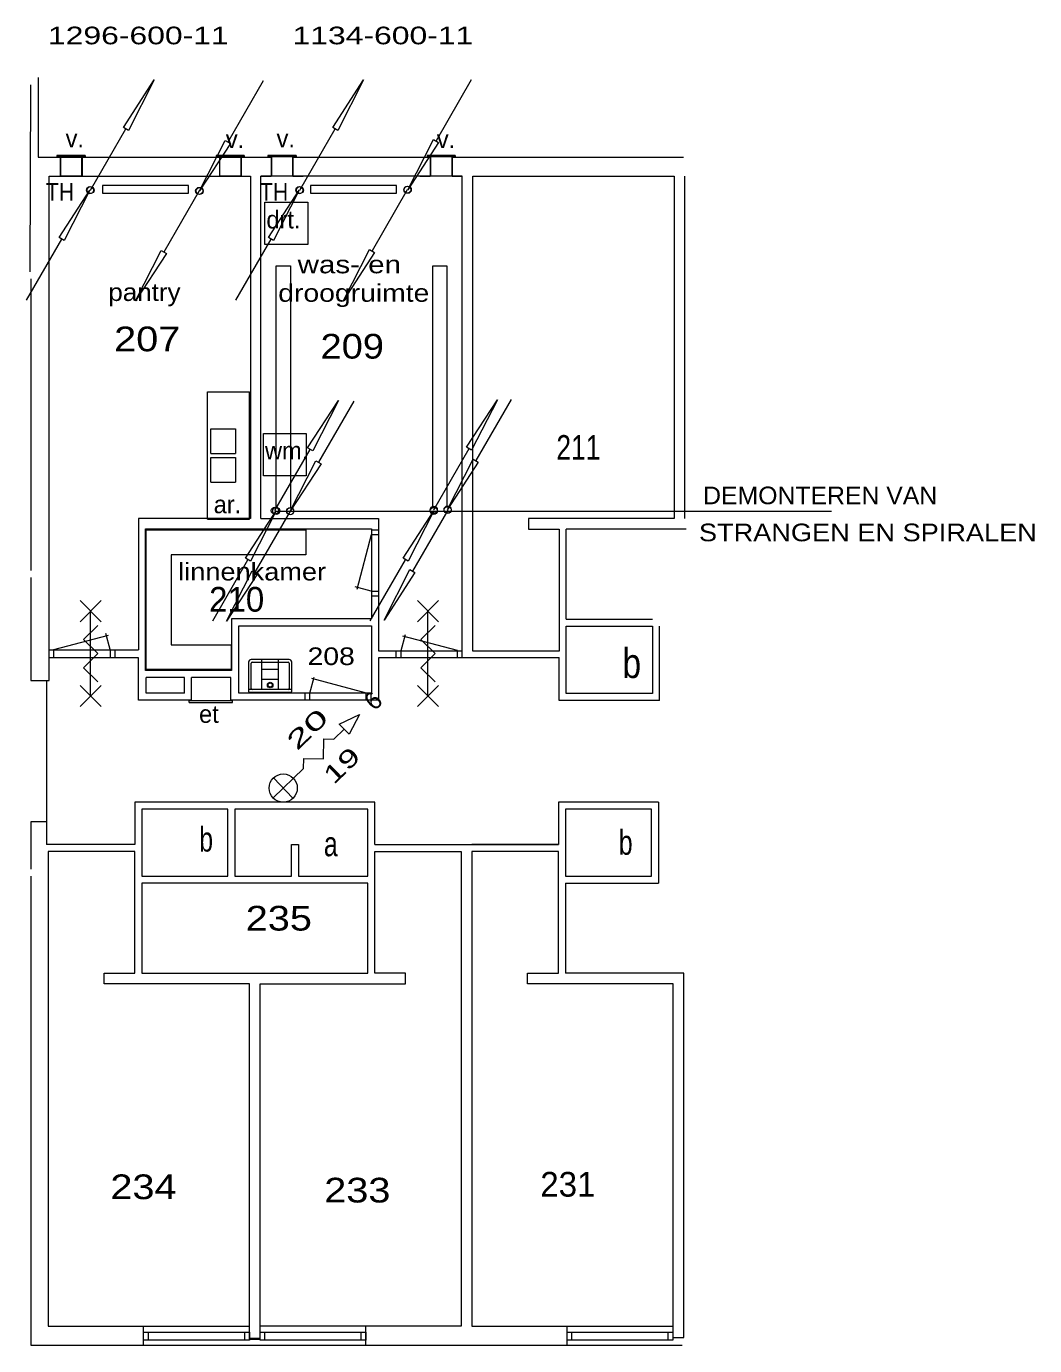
# Model space of a CAD drawing. Extents: x 295824 to 414724, y 24924 to 109024.
# Drawn here: x 361003 to 375282, y 62517 to 81204 of the extents above; entities that cross this region are included whole.
import ezdxf
from ezdxf.enums import TextEntityAlignment as Align

# ---------------------------------------------------------------- set-up
doc = ezdxf.new("R2010")
doc.units = 0
doc.header["$LTSCALE"] = 100
doc.layers.add('16', color=7, linetype='Continuous', lineweight=13)
doc.layers.add('61', color=7, linetype='Continuous', lineweight=13)

msp = doc.modelspace()

# ---------------------------------------------------------------- linework, layer by layer
at = {"layer": '16'}
for p, q in [((364356.3, 80430.9), (363856.3, 79564.9)), ((367304.4, 80447.6), (366804.4, 79581.6)), ((361912.5, 78885.4), (362412.5, 79751.4)), ((364877.3, 78885.4), (365377.3, 79751.4)), ((363450.2, 78872.9), (362950.2, 78006.9)), ((366398.3, 78889.6), (365898.3, 78023.6)), ((361003.2, 77324.8), (361503.2, 78190.8)), ((363968.1, 77324.8), (364468.1, 78190.8)), ((365640.7, 75894.7), (365140.7, 75028.7)), ((367867.8, 75918.5), (367367.8, 75052.5)), ((364522.2, 74344.5), (365022.2, 75210.5)), ((366773.1, 74356.4), (367273.1, 75222.4)), ((364738.5, 74336.4), (364238.5, 73470.4)), ((364519.8, 74337.8), (372403.9, 74337.8)), ((366970.5, 74353.1), (366470.5, 73487.1)), ((363641.4, 72782), (364141.4, 73648)), ((365873.4, 72782), (366373.4, 73648))]:
    msp.add_line(p, q, dxfattribs=at)
for points in [[(362812.5, 80444.4), (362448.5, 79730.4), (362376.5, 79772.4)], [(365777.3, 80444.4), (365413.3, 79730.4), (365341.3, 79772.4)], [(363456.3, 78871.9), (363820.3, 79585.9), (363892.3, 79543.9)], [(366404.4, 78888.6), (366768.4, 79602.6), (366840.4, 79560.6)], [(361903.2, 78883.8), (361539.2, 78169.8), (361467.2, 78211.8)], [(362080.8, 78843), (363297.5, 78843), (363297.5, 78950.2), (362080.8, 78950.2)], [(364868.1, 78883.8), (364504.1, 78169.8), (364432.1, 78211.8)], [(365026.2, 78843), (366242.9, 78843), (366242.9, 78950.2), (365026.2, 78950.2)], [(362550.2, 77313.9), (362914.2, 78027.9), (362986.2, 77985.9)], [(365498.3, 77330.6), (365862.3, 78044.6), (365934.3, 78002.6)], [(365422.2, 75903.5), (365058.2, 75189.5), (364986.2, 75231.5)], [(367673.1, 75915.4), (367309.1, 75201.4), (367237.1, 75243.4)], [(364740.7, 74335.7), (365104.7, 75049.7), (365176.7, 75007.7)], [(366967.8, 74359.5), (367331.8, 75073.5), (367403.8, 75031.5)], [(364541.4, 74341), (364177.4, 73627), (364105.4, 73669)], [(366773.4, 74341), (366409.4, 73627), (366337.4, 73669)], [(363838.5, 72777.4), (364202.5, 73491.4), (364274.5, 73449.4)], [(366070.5, 72794.1), (366434.5, 73508.1), (366506.5, 73466.1)]]:
    msp.add_lwpolyline(points, close=True, dxfattribs=at)
for points in [[(364542.5, 74378.4), (364542.5, 77810.4), (364745, 77810.4), (364745, 74390.3)], [(366757.7, 74378.4), (366757.7, 77810.4), (366960.1, 77810.4), (366960.1, 74390.3)]]:
    msp.add_lwpolyline(points, dxfattribs=at)
for centre in [(361903.2, 78883.5), (361912.5, 78885.1), (363450.2, 78873.2), (363456.3, 78872.2), (364868.1, 78883.5), (364877.3, 78885.1), (366398.3, 78889.9), (366404.4, 78888.9), (364522.2, 74344.2), (364541.4, 74340.7), (364738.5, 74336.7), (364740.7, 74336), (366773.1, 74356.1), (366773.4, 74340.7), (366967.8, 74359.8), (366970.5, 74353.4)]:
    msp.add_circle(centre, 50, dxfattribs=at)
at = {"layer": '61'}
for p, q in [((361055.1, 77727.2), (361068.1, 80377.2)), ((361168.1, 80477.2), (361168.1, 79352.1)), ((361168.1, 79352.1), (364468.2, 79352.1)), ((361833.8, 79372.3), (361435.5, 79372.3)), ((361435.5, 79372.3), (361435.5, 79357.2)), ((361833.8, 79357.2), (361435.5, 79357.2)), ((361480.2, 79352.1), (361480.2, 79082.1)), ((361485.8, 79357.2), (361485.8, 79082.8)), ((361784.5, 79357.2), (361784.5, 79082.8)), ((361790.9, 79350.8), (361790.9, 79082.3)), ((361833.8, 79372.3), (361833.8, 79357.2)), ((364087.5, 79372.3), (363689.2, 79372.3)), ((363689.2, 79372.3), (363689.2, 79357.2)), ((364087.5, 79357.2), (363689.2, 79357.2)), ((363739.5, 79357.2), (363739.5, 79082.8)), ((364038.2, 79357.2), (364038.2, 79082.8)), ((364044.6, 79350.7), (364044.6, 79080.7)), ((364087.5, 79372.3), (364087.5, 79357.2)), ((364821.8, 79372.3), (364423.5, 79372.3)), ((364423.5, 79372.3), (364423.5, 79357.2)), ((364821.8, 79357.2), (364423.5, 79357.2)), ((364468.2, 79352.1), (364468.2, 79082.1)), ((364473.7, 79357.2), (364473.7, 79082.8)), ((364772.4, 79357.2), (364772.4, 79082.8)), ((364778.9, 79350.8), (364778.9, 79082.3)), ((364778.9, 79350.8), (366721.9, 79350.8)), ((364821.8, 79372.3), (364821.8, 79357.2)), ((367075.5, 79372.3), (366677.2, 79372.3)), ((366677.2, 79372.3), (366677.2, 79357.2)), ((367075.5, 79357.2), (366677.2, 79357.2)), ((366721.9, 79350.8), (366721.9, 79082.3)), ((366727.5, 79357.2), (366727.5, 79082.8)), ((367026.2, 79357.2), (367026.2, 79082.8)), ((367032.6, 79350.7), (370310.6, 79350.7)), ((367032.6, 79350.7), (367032.6, 79080.7)), ((367075.5, 79372.3), (367075.5, 79357.2)), ((361325.1, 71936.1), (361325.1, 79080.7)), ((361784.5, 79082.8), (361485.8, 79082.8)), ((361790.9, 79082.3), (361936.7, 79082.3)), ((363587.2, 79082.3), (363733.9, 79082.3)), ((364038.2, 79082.8), (363739.5, 79082.8)), ((364325.1, 79082.1), (364468.2, 79082.1)), ((364325.1, 74230.7), (364325.1, 79080.8)), ((367175.1, 79080.8), (364325.1, 79080.8)), ((364772.4, 79082.8), (364473.7, 79082.8)), ((364778.9, 79082.3), (364924.7, 79082.3)), ((366575.2, 79082.3), (366721.9, 79082.3)), ((367026.2, 79082.8), (366727.5, 79082.8)), ((367032.6, 79080.7), (367175.1, 79080.7)), ((367175.1, 72262), (367175.1, 79080.8)), ((370325.1, 79080.7), (370325.1, 74230.7)), ((361068.1, 77627.2), (361068.1, 73497.4)), ((363615.5, 75505.1), (363965.5, 75505.1)), ((363966.4, 75503.5), (363966.4, 75153.5)), ((363965.5, 75151), (363615.5, 75151)), ((363615.5, 75096.9), (363965.5, 75096.9)), ((363966.4, 75095.3), (363966.4, 74745.3)), ((363965.5, 74742.8), (363615.5, 74742.8)), ((362590.4, 74230.7), (362590.4, 72374.6)), ((364325.1, 74230.7), (365990.4, 74230.7)), ((362690.4, 72080.4), (362690.4, 74085.4)), ((365888.4, 74001.2), (365681.4, 73228.4)), ((365989.9, 74067.4), (365889, 74067.4)), ((365987.9, 74000.4), (365890.4, 74000.4)), ((365988.3, 74067.4), (365891.6, 74067.4)), ((368650.1, 72805.7), (368650.1, 74079.4)), ((370346.5, 74079.4), (368650.1, 74079.4)), ((365887.8, 73202.8), (365660.9, 73263.5)), ((362063.4, 73069.3), (361763.4, 72769.3)), ((361763.4, 73069.3), (362063.4, 72769.3)), ((365987.7, 73200.4), (365889, 73200.4)), ((365987.9, 73133.4), (365889, 73133.4)), ((366840.6, 73069.3), (366540.6, 72769.3)), ((366540.6, 73069.3), (366840.6, 72769.3)), ((361913.4, 71719.3), (361913.4, 72919.3)), ((366690.6, 71719.3), (366690.6, 72919.3)), ((368650.1, 72805.7), (369870.1, 72805.7)), ((369970.1, 71655.7), (369970.1, 72705.7)), ((361392, 72375.2), (362164.8, 72582.3)), ((362190.5, 72375.9), (362129.7, 72602.7)), ((366311.1, 72361.5), (366371.9, 72588.4)), ((367109.5, 72360.9), (366336.8, 72567.9)), ((361392.8, 72260.6), (361392.8, 72374.6)), ((362192.8, 72260.6), (362192.8, 72374.6)), ((362259.8, 72260.6), (362259.8, 72374.6)), ((366241.8, 72261.4), (366241.8, 72360.3)), ((366308.8, 72261.6), (366308.8, 72360.3)), ((367108.8, 72261.4), (367108.8, 72360.3)), ((367175.8, 72262), (367175.8, 72360.4)), ((362590.4, 71660.4), (362590.4, 72260.6)), ((364150.7, 72199.2), (364150.7, 71784.2)), ((364725.7, 72234.2), (364185.7, 72234.2)), ((364185.7, 71824.2), (364185.7, 72184.2)), ((364200.7, 72199.2), (364710.7, 72199.2)), ((364335.7, 71809.2), (364335.7, 72234.2)), ((364575.7, 71809.2), (364575.7, 72234.2)), ((364725.7, 72184.2), (364725.7, 71824.2)), ((364760.7, 71784.2), (364760.7, 72199.2)), ((365990.4, 72262), (367178.7, 72262)), ((365990.4, 72260.4), (365990.4, 71660.4)), ((367175.1, 72262), (368550.1, 72262)), ((368550.1, 71655.7), (368550.1, 72262)), ((363910.4, 72080.4), (362690.4, 72080.4)), ((362700.4, 71760.4), (362700.4, 71980.4)), ((363240.4, 71980.4), (362700.4, 71980.4)), ((363240.4, 71760.4), (363240.4, 71980.4)), ((363340.4, 71660.4), (363340.4, 71980.4)), ((363900.4, 71980.4), (363340.4, 71980.4)), ((363900.4, 71660.4), (363900.4, 71980.4)), ((364575.7, 72092.5), (364335.7, 72092.5)), ((364575.7, 71950.8), (364335.7, 71950.8)), ((365019.8, 71760.5), (365080.6, 71987.4)), ((365818.2, 71759.9), (365045.5, 71966.9)), ((361288.1, 71936.1), (361288.1, 69616.5)), ((362063.4, 71869.3), (361763.4, 71569.3)), ((361763.4, 71869.3), (362063.4, 71569.3)), ((363240.4, 71760.4), (362700.4, 71760.4)), ((364750.7, 71809.2), (364160.7, 71809.2)), ((364160.7, 71774.2), (364750.7, 71774.2)), ((364950.5, 71660.4), (364950.5, 71759.3)), ((365017.5, 71660.6), (365017.5, 71759.3)), ((365817.5, 71660.4), (365817.5, 71759.3)), ((365884.5, 71660.4), (365884.5, 71759.3)), ((366840.6, 71869.3), (366540.6, 71569.3)), ((366540.6, 71869.3), (366840.6, 71569.3)), ((363340.4, 71660.4), (362590.4, 71660.4)), ((363306.2, 71653.3), (363924.6, 71653.3)), ((363306.2, 71625.6), (363306.2, 71653.3)), ((365990.4, 71660.4), (363900.4, 71660.4)), ((369970.1, 71655.7), (368550.1, 71655.7)), ((364501.1, 70558.2), (364779, 70270.4)), ((362537.4, 70216.5), (362537.4, 69616.5)), ((365937.4, 70216.5), (362537.4, 70216.5)), ((365937.4, 69616.5), (365937.4, 70216.5)), ((369957.4, 70216.5), (369957.4, 69066.5)), ((362537.4, 69616.5), (361288.1, 69616.5)), ((361068.1, 69167.6), (361068.1, 62521.5)), ((368637.4, 69066.5), (368637.4, 67791.9)), ((368637.4, 69066.5), (369957.4, 69066.5)), ((370312.4, 67791.9), (368637.4, 67791.9)), ((370312.4, 62630.9), (370312.4, 67791.9)), ((361312.4, 62791.5), (364162.4, 62791.5)), ((367162.4, 62791.5), (364312.4, 62791.5)), ((367312.4, 62791.5), (370162.4, 62791.5)), ((368660.5, 62519.4), (368660.5, 62789.4)), ((362663.7, 62516.8), (362663.7, 62786.8)), ((362730.4, 62595.1), (362730.4, 62709)), ((364095.4, 62594.5), (364095.4, 62708.5)), ((364162.4, 62624.5), (364312.4, 62624.5)), ((364162.4, 62609.5), (364312.4, 62609.5)), ((364378.9, 62595.5), (364378.9, 62709.5)), ((365743.2, 62595.2), (365743.2, 62708.8)), ((365811.7, 62516.8), (365811.7, 62787)), ((368727.3, 62595.1), (368727.3, 62709)), ((370092.3, 62594.5), (370092.3, 62708.5)), ((370160.9, 62630.9), (370312.4, 62630.9)), ((361068.1, 62521.5), (370292.2, 62521.5))]:
    msp.add_line(p, q, dxfattribs=at)
for points in [[(361325.1, 79080.7), (364175.1, 79080.7), (364175.1, 74230.7), (362590.4, 74230.7)], [(363567.3, 74225.2), (364162, 74225.2), (364162, 76025.2)], [(363567.3, 74225.2), (363567.3, 76025.2), (364162, 76025.2)], [(363616.4, 75153.5), (363616.4, 75503.5), (363615.5, 75505.1)], [(363616.4, 74745.3), (363616.4, 75095.3), (363615.5, 75096.9)], [(365990.4, 74230.7), (365990.4, 72360.4), (367175.8, 72360.4)], [(362690.4, 74085.4), (365890.4, 74085.4), (365890.4, 72810.4), (363910.4, 72810.4), (363910.4, 72080.4)], [(361068.1, 73397.4), (361068.1, 71936.1), (361325.1, 71936.1)], [(362013.4, 71919.3), (361813.4, 72119.3), (362013.4, 72319.3), (361813.4, 72519.3), (362013.4, 72719.3)], [(366790.6, 71919.3), (366590.6, 72119.3), (366790.6, 72319.3), (366590.6, 72519.3), (366790.6, 72719.3)], [(361325.8, 72260.6), (361325.8, 72374.6), (362590.4, 72374.6)], [(362590.4, 72260.6), (361325.8, 72260.6), (361325.8, 72374.6)], [(363306.2, 71625.6), (363924.6, 71625.6), (363924.6, 71653.3)], [(364496.2, 70275.4), (364927.8, 70692.2), (364930.2, 70833.6), (365213, 70828.6), (365218, 71111.4), (365359.4, 71109), (365503.2, 71247.9)], [(369957.4, 70216.5), (368537.4, 70216.5), (368537.4, 69616.5)], [(361288.1, 69936.1), (361068.1, 69936.1), (361068.1, 69267.6)], [(364162.4, 62609.5), (364162.4, 67641.5), (362102.4, 67641.5), (362102.4, 67791.5), (362537.4, 67791.5), (362537.4, 69516.5), (361312.4, 69516.5), (361312.4, 62791.5)], [(364312.4, 62609.5), (364312.4, 67641.5), (366372.4, 67641.5), (366372.4, 67791.5), (365937.4, 67791.5), (365937.4, 69516.5), (367162.4, 69516.5), (367162.4, 62791.5)], [(365937.4, 69616.5), (368537.4, 69616.5), (367312.4, 69616.5)], [(370162.4, 62630.9), (370162.4, 67641.5), (368102.4, 67641.5), (368102.4, 67791.5), (368537.4, 67791.5), (368537.4, 69516.5), (367312.4, 69516.5), (367312.4, 62791.5)]]:
    msp.add_lwpolyline(points, dxfattribs=at)
for points in [[(367325.1, 79080.7), (370175.1, 79080.7), (370175.1, 74230.7), (368115.1, 74230.7), (368115.1, 74080.7), (368550.1, 74080.7), (368550.1, 72355.7), (367325.1, 72355.7)], [(364382.4, 78115.6), (364382.4, 78715.6), (364986.8, 78715.6), (364986.8, 78115.6)], [(364362.7, 74835.5), (364362.7, 75435.5), (364967.2, 75435.5), (364967.2, 74835.5)], [(362712.9, 74070.1), (364960.1, 74070.1), (364960.1, 73720.1), (363054.4, 73720.1), (363054.4, 72442.9), (363902.1, 72442.9), (363902.1, 72092.9), (362700.6, 72092.9), (362700.6, 74070.1)], [(364010.4, 72710.4), (365890.4, 72710.4), (365890.4, 71760.4), (364010.4, 71760.4)], [(368650.1, 72705.7), (369870.1, 72705.7), (369870.1, 71755.7), (368650.1, 71755.7)], [(365572.7, 71176), (365433.8, 71319.8), (365719, 71456.3)], [(362637.4, 69166.5), (363857.4, 69166.5), (363857.4, 70116.5), (362637.4, 70116.5)], [(363957.4, 69166.5), (364757.4, 69166.5), (364757.4, 69616.5), (364857.4, 69616.5), (364857.4, 69166.5), (365837.4, 69166.5), (365837.4, 70116.5), (363957.4, 70116.5)], [(368637.4, 69166.5), (369857.4, 69166.5), (369857.4, 70116.5), (368637.4, 70116.5)], [(362637.4, 67791.5), (365837.4, 67791.5), (365837.4, 69066.5), (362637.4, 69066.5)], [(362663.6, 62595), (362663.6, 62709), (364162.2, 62709), (364162.2, 62595)], [(364312.6, 62595.2), (364312.6, 62709.2), (365812, 62709.2), (365812, 62595.2)], [(368660.5, 62595), (368660.5, 62709), (370159.1, 62709), (370159.1, 62595)]]:
    msp.add_lwpolyline(points, close=True, dxfattribs=at)
for centre, radius in [((364455.7, 71874.2), 40), ((364455.7, 71874.2), 30), ((364640, 70414.3), 200)]:
    msp.add_circle(centre, radius, dxfattribs=at)
for centre, radius, start, end in [((364185.7, 72199.2), 35, 90, 180), ((364200.7, 72184.2), 15, 90, 180), ((364710.7, 72184.2), 15, 0, 90), ((364725.7, 72199.2), 35, 0, 90), ((364160.7, 71799.2), 10, 90, 180), ((364160.7, 71784.2), 10, 180, 270), ((364200.7, 71824.2), 15, 180, 270), ((364710.7, 71824.2), 15, 270, 0), ((364750.7, 71799.2), 10, 0, 90), ((364750.7, 71784.2), 10, 270, 0)]:
    msp.add_arc(centre, radius, start, end, dxfattribs=at)

# ---------------------------------------------------------------- texts
at = {"layer": '16'}
for s, width, p in [('1296-600-11', 1.35, (361308.9, 80949.8)), ('1134-600-11', 1.35, (364772.6, 80949.8)), ('TH', 0.9, (361278.9, 78733.9)), ('TH', 0.9, (364310.4, 78733.9)), ('DEMONTEREN VAN', 1.05, (370587.6, 74434.7)), ('STRANGEN EN SPIRALEN', 1.15, (370528.1, 73910.3))]:
    msp.add_text(s, height=250, dxfattribs=dict(at, width=width)).set_placement(p)
at = {"layer": '61'}
for s, p in [('v.', (361558.8, 79490.7)), ('v.', (363828, 79480.6)), ('v.', (364546.8, 79490.7)), ('v.', (366816, 79480.6)), ('drt.', (364402, 78341.8)), ('wm.', (364382.4, 75069.1)), ('ar.', (363655.8, 74307.5)), ('et', (363448.7, 71338.4))]:
    msp.add_text(s, height=250, dxfattribs=at).set_placement(p)
for s, width, p in [('was- en', 1.25, (364845.2, 77706.1)), ('droogruimte', 1.2, (364569.9, 77302.8)), ('pantry', 1.1, (362164.2, 77314.1)), ('linnenkamer', 1.15, (363153.4, 73355.2))]:
    msp.add_text(s, height=250, dxfattribs=dict(at, width=width)).set_placement(p)
for s, height, width, p in [('207', 350, 1.2, (362714.5, 76601.4)), ('209', 350, 1.15, (365618.3, 76497.7)), ('211', 350, 0.8, (368821.1, 75063.9)), ('208', 250, 1.2, (365319.7, 72156.8)), ('b', 420, 0.85, (369576.3, 71973.7)), ('b', 350, 0.75, (363549.6, 69514.7)), ('a', 350, 0.75, (365314.4, 69448.8)), ('b', 350, 0.75, (369491.2, 69469.2)), ('235', 350, 1.2, (364578.5, 68395.9)), ('234', 350, 1.2, (362661.4, 64591.3)), ('233', 350, 1.2, (365690.3, 64544.1))]:
    msp.add_text(s, height=height, dxfattribs=dict(at, width=width)).set_placement(p, align=Align.CENTER)
for s, p in [('210', (363981.1, 72913.1)), ('231', (368671.7, 64627.1))]:
    msp.add_text(s, height=350, dxfattribs=at).set_placement(p, align=Align.CENTER)
msp.add_text('6', height=250, rotation=44, dxfattribs=at).set_placement((365934.3, 71498.4))
for s, width, p in [('20', 1.75, (364834.3, 70933.5)), ('19', 1.5, (365354.5, 70452.1))]:
    msp.add_text(s, height=250, rotation=44, dxfattribs=dict(at, width=width)).set_placement(p)

doc.saveas('drawing.dxf')
